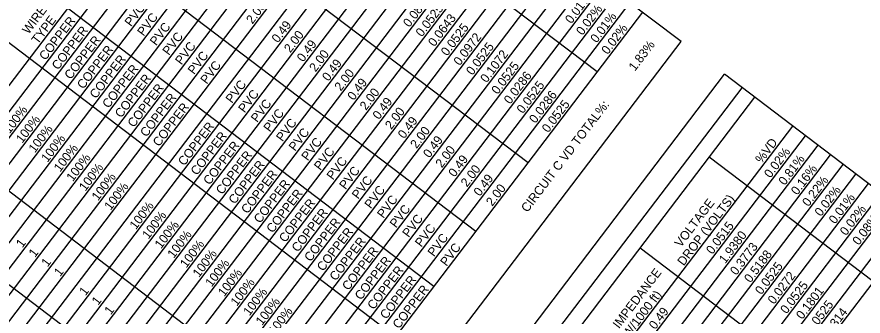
# Model space of a CAD drawing. Extents: x 1289840 to 1300285, y 220865 to 232461.
# Drawn here: x 1299156 to 1299781, y 231745 to 231966 of the extents above; entities that cross this region are included whole.
import ezdxf

# ---------------------------------------------------------------- set-up
doc = ezdxf.new("R2010")
doc.units = 0
doc.layers.add('Default', color=7, linetype='Continuous')

msp = doc.modelspace()

# ---------------------------------------------------------------- linework, layer by layer
at = {"layer": 'Default'}
for p, q in [((1299646.6, 231947.46), (1299297.82, 232212.68)), ((1298829.72, 231492.71), (1299348.11, 232174.44)), ((1298839.03, 231485.63), (1299357.43, 232167.36)), ((1298848.34, 231478.55), (1299366.74, 232160.28)), ((1298857.66, 231471.46), (1299376.05, 232153.19)), ((1299584.56, 231924.83), (1299286.54, 232151.45)), ((1298866.97, 231464.38), (1299385.37, 232146.11)), ((1298876.28, 231457.3), (1299394.68, 232139.03)), ((1298885.6, 231450.22), (1299403.99, 232131.95)), ((1298894.91, 231443.14), (1299413.31, 232124.87)), ((1298904.22, 231436.05), (1299422.62, 232117.78)), ((1298913.54, 231428.97), (1299431.93, 232110.7)), ((1298922.85, 231421.89), (1299441.25, 232103.62)), ((1298932.16, 231414.81), (1299450.56, 232096.54)), ((1298941.48, 231407.73), (1299459.87, 232089.46)), ((1298950.79, 231400.64), (1299469.19, 232082.37)), ((1299533.57, 231857.77), (1299235.55, 232084.39)), ((1298960.1, 231393.56), (1299478.5, 232075.29)), ((1298969.42, 231386.48), (1299487.81, 232068.21)), ((1298978.73, 231379.4), (1299497.13, 232061.13)), ((1298988.04, 231372.32), (1299506.44, 232054.05)), ((1298997.36, 231365.24), (1299515.75, 232046.96)), ((1299006.67, 231358.15), (1299525.07, 232039.88)), ((1299015.98, 231351.07), (1299534.38, 232032.8)), ((1299494.97, 231807.01), (1299196.95, 232033.63)), ((1299025.3, 231343.99), (1299543.69, 232025.72)), ((1299034.61, 231336.91), (1299553.01, 232018.64)), ((1299043.92, 231329.83), (1299562.32, 232011.55)), ((1299053.24, 231322.74), (1299571.63, 232004.47)), ((1299062.55, 231315.66), (1299580.95, 231997.39)), ((1299071.86, 231308.58), (1299590.26, 231990.31)), ((1299464.17, 231766.5), (1299166.14, 231993.12)), ((1299081.18, 231301.5), (1299599.57, 231983.23)), ((1299090.49, 231294.42), (1299608.89, 231976.15)), ((1299099.8, 231287.33), (1299618.2, 231969.06)), ((1299435.84, 231729.25), (1299137.82, 231955.87)), ((1299128.21, 231265.73), (1299646.6, 231947.46)), ((1299160.21, 231241.4), (1299678.61, 231923.13)), ((1300018.07, 231664.99), (1299678.61, 231923.13)), ((1299173.25, 231231.49), (1299691.64, 231913.21)), ((1299182.56, 231224.4), (1299700.96, 231906.13)), ((1299383.08, 231659.86), (1299085.05, 231886.49)), ((1299210.5, 231203.16), (1299728.9, 231884.89)), ((1299219.81, 231196.08), (1299738.21, 231877.8)), ((1299229.13, 231188.99), (1299747.52, 231870.72)), ((1299238.44, 231181.91), (1299756.84, 231863.64)), ((1299956.03, 231642.36), (1299667.32, 231861.89)), ((1299247.75, 231174.83), (1299766.15, 231856.56)), ((1299257.07, 231167.75), (1299775.46, 231849.48)), ((1299349.79, 231616.09), (1299051.77, 231842.71)), ((1299266.38, 231160.67), (1299784.78, 231842.4)), ((1299275.69, 231153.58), (1299794.09, 231835.31)), ((1299285.01, 231146.5), (1299803.4, 231828.23)), ((1299294.32, 231139.42), (1299812.72, 231821.15)), ((1299303.63, 231132.34), (1299822.03, 231814.07)), ((1299905.04, 231575.3), (1299616.33, 231794.84))]:
    msp.add_line(p, q, dxfattribs=at)

# ---------------------------------------------------------------- texts
for s, p in [('0.0858', (1299445.97, 231957.38)), ('0.01%', (1299565.55, 231959.99)), ('2.00', (1299330.25, 231959.83)), ('WIRE', (1299165.07, 231952.26)), ('PVC', (1299240.61, 231957.92)), ('0.0525', (1299455.29, 231950.3)), ('0.02%', (1299573.73, 231951.42)), ('TYPE', (1299171.88, 231944.87)), ('COPPER', (1299177.53, 231932.96)), ('PVC', (1299249.92, 231950.84)), ('0.0643', (1299464.51, 231943.09)), ('0.01%', (1299584.17, 231945.83)), ('COPPER', (1299186.85, 231925.88)), ('PVC', (1299259.23, 231943.76)), ('0.49', (1299349.03, 231945.87)), ('0.0525', (1299473.91, 231936.14)), ('0.02%', (1299592.35, 231937.26)), ('COPPER', (1299196.16, 231918.8)), ('PVC', (1299268.55, 231936.68)), ('2.00', (1299358.18, 231938.58)), ('0.0972', (1299483.23, 231929.05)), ('PVC', (1299277.86, 231929.6)), ('0.49', (1299367.66, 231931.7)), ('0.0525', (1299492.54, 231921.97)), ('1.83%', (1299612.43, 231925)), ('COPPER', (1299205.47, 231911.72)), ('PVC', (1299287.17, 231922.51)), ('2.00', (1299376.81, 231924.42)), ('0.1072', (1299502.99, 231916.38)), ('COPPER', (1299214.79, 231904.64)), ('PVC', (1299296.49, 231915.43)), ('0.49', (1299386.28, 231917.54)), ('0.0525', (1299511.17, 231907.81)), ('COPPER', (1299224.1, 231897.55)), ('2.00', (1299395.44, 231910.25)), ('COPPER', (1299233.41, 231890.47)), ('0.49', (1299404.91, 231903.38)), ('0.0286', (1299520.37, 231900.58)), ('COPPER', (1299242.73, 231883.39)), ('PVC', (1299315.11, 231901.27)), ('0.0525', (1299529.79, 231893.64)), ('COPPER', (1299252.04, 231876.31)), ('PVC', (1299324.43, 231894.19)), ('2.00', (1299414.06, 231896.09)), ('0.0286', (1299539, 231886.42)), ('COPPER', (1299261.35, 231869.23)), ('PVC', (1299333.74, 231887.1)), ('0.49', (1299423.53, 231889.21)), ('CIRCUIT C VD TOTAL%:', (1299533.1, 231820.68)), ('0.0525', (1299548.42, 231879.48)), ('100%', (1299151.08, 231878.85)), ('PVC', (1299343.05, 231880.02)), ('2.00', (1299432.69, 231881.92)), ('100%', (1299160.4, 231871.77)), ('PVC', (1299352.37, 231872.94)), ('0.49', (1299442.16, 231875.05)), ('100%', (1299169.71, 231864.69)), ('COPPER', (1299279.98, 231855.06)), ('PVC', (1299361.68, 231865.86)), ('2.00', (1299451.32, 231867.76)), ('100%', (1299179.02, 231857.61)), ('COPPER', (1299289.29, 231847.98)), ('PVC', (1299370.99, 231858.78)), ('0.49', (1299460.79, 231860.89)), ('100%', (1299188.34, 231850.52)), ('COPPER', (1299298.61, 231840.9)), ('2.00', (1299469.94, 231853.6)), ('%VD', (1299705.88, 231856.8)), ('100%', (1299197.65, 231843.44)), ('COPPER', (1299307.92, 231833.82)), ('PVC', (1299380.31, 231851.69)), ('0.49', (1299479.41, 231846.72)), ('0.02%', (1299712.37, 231846)), ('0.81%', (1299722.97, 231840.61)), ('100%', (1299206.96, 231836.36)), ('COPPER', (1299317.23, 231826.74)), ('PVC', (1299389.62, 231844.61)), ('COPPER', (1299326.55, 231819.65)), ('PVC', (1299398.93, 231837.53)), ('2.00', (1299488.57, 231839.43)), ('0.16%', (1299732.19, 231833.41)), ('100%', (1299216.28, 231829.28)), ('COPPER', (1299335.86, 231812.57)), ('PVC', (1299408.25, 231830.45)), ('0.49', (1299498.04, 231832.56)), ('0.22%', (1299740.46, 231824.96)), ('100%', (1299225.59, 231822.2)), ('PVC', (1299417.56, 231823.37)), ('2.00', (1299507.2, 231825.27)), ('0.02%', (1299749.62, 231817.67)), ('COPPER', (1299345.17, 231805.49)), ('PVC', (1299426.87, 231816.28)), ('DROP (VOLTS)', (1299648.39, 231781.2)), ('0.01%', (1299760.06, 231812.08)), ('100%', (1299244.22, 231808.03)), ('COPPER', (1299354.48, 231798.41)), ('PVC', (1299436.19, 231809.2)), ('VOLTAGE ', (1299646.33, 231794.84)), ('0.02%', (1299768.25, 231803.51)), ('100%', (1299253.53, 231800.95)), ('COPPER', (1299363.8, 231791.33)), ('PVC', (1299445.5, 231802.12)), ('100%', (1299262.84, 231793.87)), ('COPPER', (1299373.11, 231784.24)), ('0.0515', (1299669.56, 231789.71)), ('0.08%', (1299777.56, 231796.42)), ('100%', (1299272.16, 231786.79)), ('COPPER', (1299382.42, 231777.16)), ('PVC', (1299454.81, 231795.04)), ('1.9380', (1299679.02, 231782.81)), ('1', (1299160.49, 231794.58)), ('COPPER', (1299391.74, 231770.08)), ('PVC', (1299464.13, 231787.96)), ('100%', (1299281.47, 231779.7)), ('COPPER', (1299401.05, 231763)), ('PVC', (1299473.44, 231780.87)), ('0.3773', (1299687.21, 231774.26)), ('1', (1299169.81, 231787.5)), ('100%', (1299290.78, 231772.62)), ('COPPER', (1299410.36, 231755.92)), ('0.5188', (1299697.66, 231768.67)), ('1', (1299179.12, 231780.42)), ('100%', (1299300.1, 231765.54)), ('0.0525', (1299705.68, 231759.89)), ('1', (1299188.43, 231773.33)), ('100%', (1299309.41, 231758.46)), ('COPPER', (1299419.68, 231748.83)), ('IMPEDANCE', (1299600.72, 231734.86)), ('0.0272', (1299715, 231752.81)), ('100%', (1299318.72, 231751.38)), ('COPPER', (1299428.99, 231741.75)), ('0.0525', (1299724.31, 231745.73)), ('1', (1299207.06, 231759.17)), ('100%', (1299328.04, 231744.3)), ('COPPER', (1299438.3, 231734.67)), ('0.1801', (1299735.89, 231741.63)), ('1', (1299216.37, 231752.09)), ('100%', (1299337.35, 231737.21)), ('(W/1000 ft)', (1299606.11, 231725.6)), ('1', (1299225.69, 231745.01)), ('0.0525', (1299742.94, 231731.57)), ('100%', (1299346.66, 231730.13)), ('0.49', (1299627.37, 231734.22)), ('0.0314', (1299753.38, 231725.97))]:
    msp.add_text(s, height=6.6, rotation=52.75013, dxfattribs=at).set_placement(p)

doc.saveas('drawing.dxf')
